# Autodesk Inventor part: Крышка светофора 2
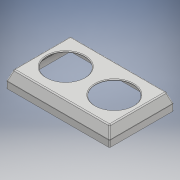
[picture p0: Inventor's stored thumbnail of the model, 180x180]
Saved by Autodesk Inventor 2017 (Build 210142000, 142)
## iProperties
Part Number: Крышка светофора 2
Material: Типовые
Document SubType Name: Modeling
Designer: Система Знаний
Density: 1 g/cm^3
Appearance: По умолчанию
Author: Система Знаний
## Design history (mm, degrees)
sketch "Эскиз1"
  geometry: L1 (0, 0)-(317.5, 0); L2 (317.5, 0)-(317.5, -197.5); L3 (317.5, -197.5)-(0, -197.5); L4 (0, -197.5)-(0, 0)
  constraints: 8 end point, 2 parallel, 1 horizontal, 1 perpendicular
  dimensions: "d0" = 317.5 distance of L2.end L3.end; "d1" = 197.5 distance of L1.end L2.end
extrude "Выдавливание1" new body sketch "Эскиз1" distance "d2" = 28.7; taper "d3" = 0 deg
feature "НаклГрань1" dims angle "d4" = 20.5 deg
sketch "Эскиз7"
  geometry: L1 (0, 0)-(-317.5, 0) reference; L2 (0, -197.5)-(-317.5, -197.5); L3 (-317.5, -197.5)-(-317.5, 0); L4 (-317.5, 0)-(0, 0); L5 (0, 0)-(0, -197.5)
  constraints: 8 end point, 2 parallel, 1 horizontal, 1 perpendicular
extrude "Выдавливание2" join sketch "Эскиз7" distance "d7" = 20; taper "d8" = 0 deg
feature "Оболочка1" dims "d9" = 1.7
sketch "Эскиз8"
  geometry: L1 (10.73, -186.77)-(10.73, -10.73) reference; L2 (10.73, -10.73)-(306.77, -10.73); L3 (306.77, -10.73)-(306.77, -186.77); L4 (306.77, -186.77)-(10.73, -186.77); L5 (10.73, -186.77)-(10.73, -10.73); 1 further point
  constraints: 8 end point, 2 parallel, 1 horizontal, 1 perpendicular
extrude "Выдавливание3" join sketch "Эскиз8" distance "d10" = 1.3; taper "d11" = -20.5 deg
fillet "Сопряжение1" dims "d12" = 4
fillet "Сопряжение2" dims "d13" = 4
sketch "Эскиз10"
  geometry: C1 r 60 at (83.991, -98.7); C2 r 60 at (233.509, -98.734); 1 further point
  constraints: 2 centre point
hole "Отверстие1" sketch "Эскиз10" at (233.509, -98.734), (83.991, -98.7) diameter "d22" = 116; stored, may be unused: countersink angle "d26" = 90 deg, drill point angle "d28" = 118 deg; dims "d23" = 6, "d24" = 120, "d25" = 2, "d27" = 8
node "Твердое тело1"
